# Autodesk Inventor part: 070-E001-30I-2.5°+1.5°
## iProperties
Created: 2007-11
Part Number: 070-E001-30I-2.5°+1.5°
Material: Steel, Mild
Document SubType Name: Sheet Metal
Designer: T.Baumann
Description: Gehäuse
Mass: 12331.7 g
Surface Area: 25198.7 cm^2
Volume: 1568.92 cm^3
Density: 7.86 g/cm^3
Checked By: Fa. Kontech
User Status: Bei Fa. Kontech
Materiaal_1: Stahlblech
Materiaal_2: t = 1,25 mm
Product Code: C08
Finish_1: verzinkt
Author: T.Baumann
Revision Number: 01
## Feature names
1. Spiegeln4 [Mirror]
2. Rechteckige Anordnung3 [Rectangular Pattern]
3. Rechteckige Anordnung4 [Rectangular Pattern]
4. Rechteckige Anordnung5 [Rectangular Pattern]
5. Spiegeln7 [Mirror]
6. Grobblech1
7. Grobblech2
8. Biegung1
9. Grobblech4
10. Biegung3
11. Ausklinkung10
12. Ausklinkung11
